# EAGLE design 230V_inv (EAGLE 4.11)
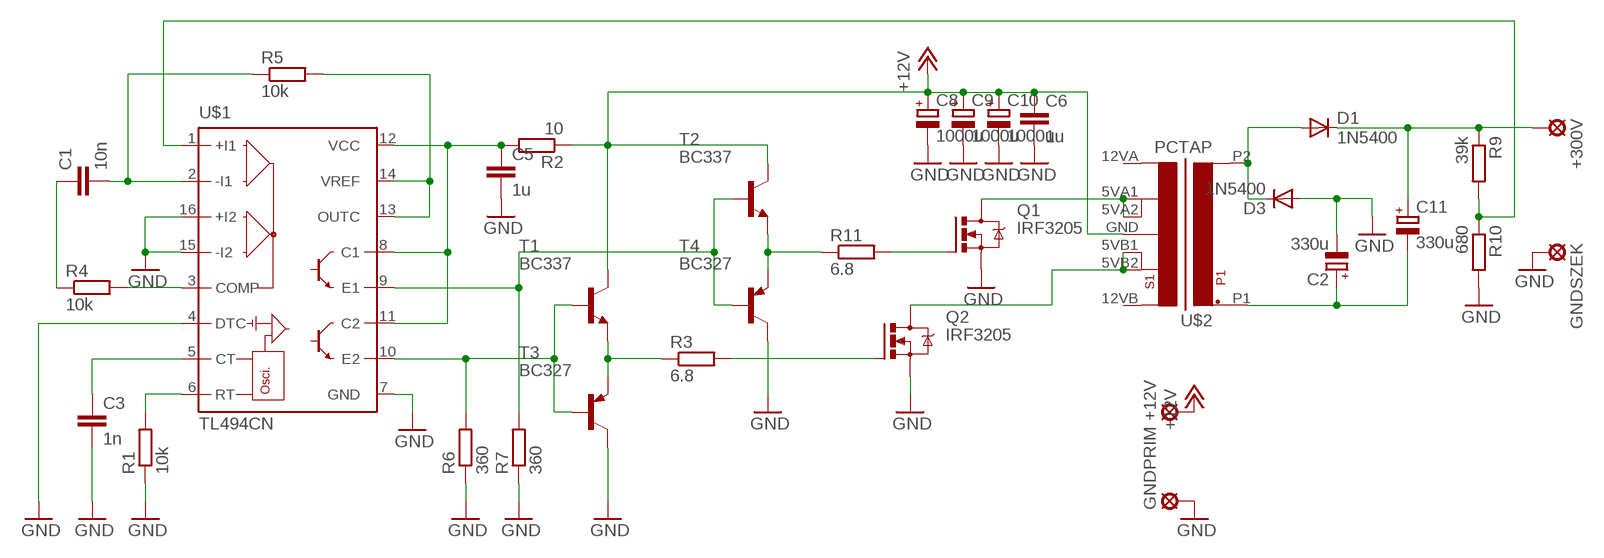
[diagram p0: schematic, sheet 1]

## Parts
+12V  SE14  [SE14]
+300V  SE14  [SE14]
C1  10n  C-EU025-025X050  [C025-025X050]
C2  330u  CPOL-EUE10-20  [EB20D]
C3  1n  C-EU025-025X050  [C025-025X050]
C5  1u  C-EU025-040X050  [C025-040X050]
C6  1u  C-EU025-040X050  [C025-040X050]
C8  1000u  CPOL-EUE5-10.5  [E5-10,5]
C9  1000u  CPOL-EUE5-10.5  [E5-10,5]
C10  1000u  CPOL-EUE5-10.5  [E5-10,5]
C11  330u  CPOL-EUE10-20  [EB20D]
D1  1N5400  [DO201-15]
D3  1N5400  [DO201-15]
GNDPRIM  SE14  [SE14]
GNDSZEK  SE14  [SE14]
Q1  IRF3205  IRF540  [TO220BV]
Q2  IRF3205  IRF540  [TO220BV]
R1  10k  R-EU_0204/5  [0204/5]
R2  10  R-EU_0204/5  [0204/5]
R3  6.8  R-EU_0204/5  [0204/5]
R4  10k  R-EU_0204/5  [0204/5]
R5  10k  R-EU_0204/5  [0204/5]
R6  360  R-EU_0204/5  [0204/5]
R7  360  R-EU_0204/5  [0204/5]
R9  39k  R-EU_0204/5  [0204/5]
R10  680  R-EU_0204/5  [0204/5]
R11  6.8  R-EU_0207/10  [0207/10]
T1  BC337  BC337-16-NPN-TO92-EBC  [TO92-EBC]
T2  BC337  BC337-16-NPN-TO92-EBC  [TO92-EBC]
T3  BC327  BC327-16-PNP-TO92-EBC  [TO92-EBC]
T4  BC327  BC327-16-PNP-TO92-EBC  [TO92-EBC]
U$1  TL494CN  [DIL16]
U$2  PCTAP  [PCTAP]

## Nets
+12V: +12V.MP C6.1 C8.+ C9.+ C10.+ R2.1 T1.C T2.C U$2.GND
GND: C2.- C3.2 C5.2 C6.2 C8.- C9.- C10.- D3.A GNDPRIM.MP GNDSZEK.MP Q1.S Q2.S R1.1 R6.1 R7.1 R10.2 T3.C T4.C U$1.4(DTC) U$1.7(GND) U$1.15(-I2) U$1.16(+I2)
N$1: R1.2 U$1.6(RT)
N$2: C3.1 U$1.5(CT)
N$3: R4.2 U$1.3(COMP)
N$4: C1.1 R4.1
N$5: C1.2 R5.1 U$1.2(-I1)
N$6: Q2.G R3.2
N$7: R5.2 U$1.13(OUTC) U$1.14(VREF)
N$8: C5.1 R2.2 U$1.8(C1) U$1.11(C2) U$1.12(VCC)
N$9: R6.2 T1.B T3.B U$1.10(E2)
N$10: Q1.G R11.2
N$11: D1.A D3.C U$2.P2
N$12: R3.1 T1.E T3.E
N$13: R7.2 T2.B T4.B U$1.9(E1)
N$14: R11.1 T2.E T4.E
N$15: C2.+ C11.- U$2.P1
N$16: +300V.MP C11.+ D1.C R9.1
N$18: Q2.D U$2.5VB1 U$2.5VB2
N$20: R9.2 R10.1 U$1.1(+I1)
N$22: Q1.D U$2.5VA1 U$2.5VA2
Unconnected: U$2.12VA U$2.12VB

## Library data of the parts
+12V +300V GNDPRIM GNDSZEK = solpad:SE14: SOLDER PAD
C1 C3 C5 C6 = rcl:C-EU: CAPACITOR, European symbol
C2 C8-C11 = rcl:CPOL-EU: POLARIZED CAPACITOR, European symbol
D1 D3 = diode:1N5400: DIODE
Q1 Q2 = transistor-power:IRF540: HEXFET Power MOSFET
R1-R7 R9-R11 = rcl:R-EU_: RESISTOR, European symbol
T1 T2 = transistor:*-NPN-: NPN Transistror
T3 T4 = transistor:*-PNP-: PNP Transistror
U$1 = linear:TL494*: SWITCHMODE Pulse Width Modulation Control Circuit NCV494B http://onsemi.com tl494-d.pdf
U$2 = trafo:PCTAP

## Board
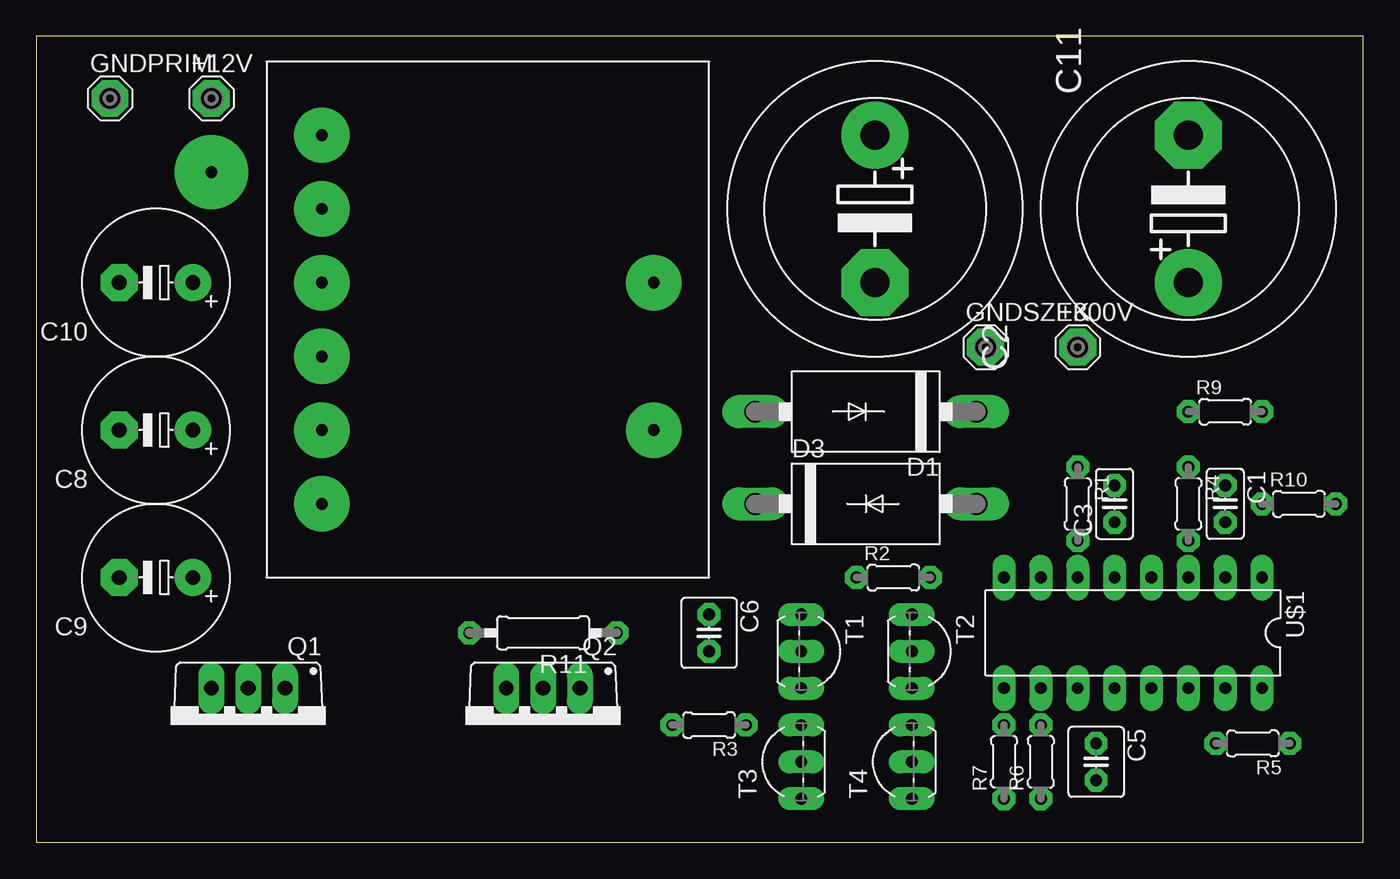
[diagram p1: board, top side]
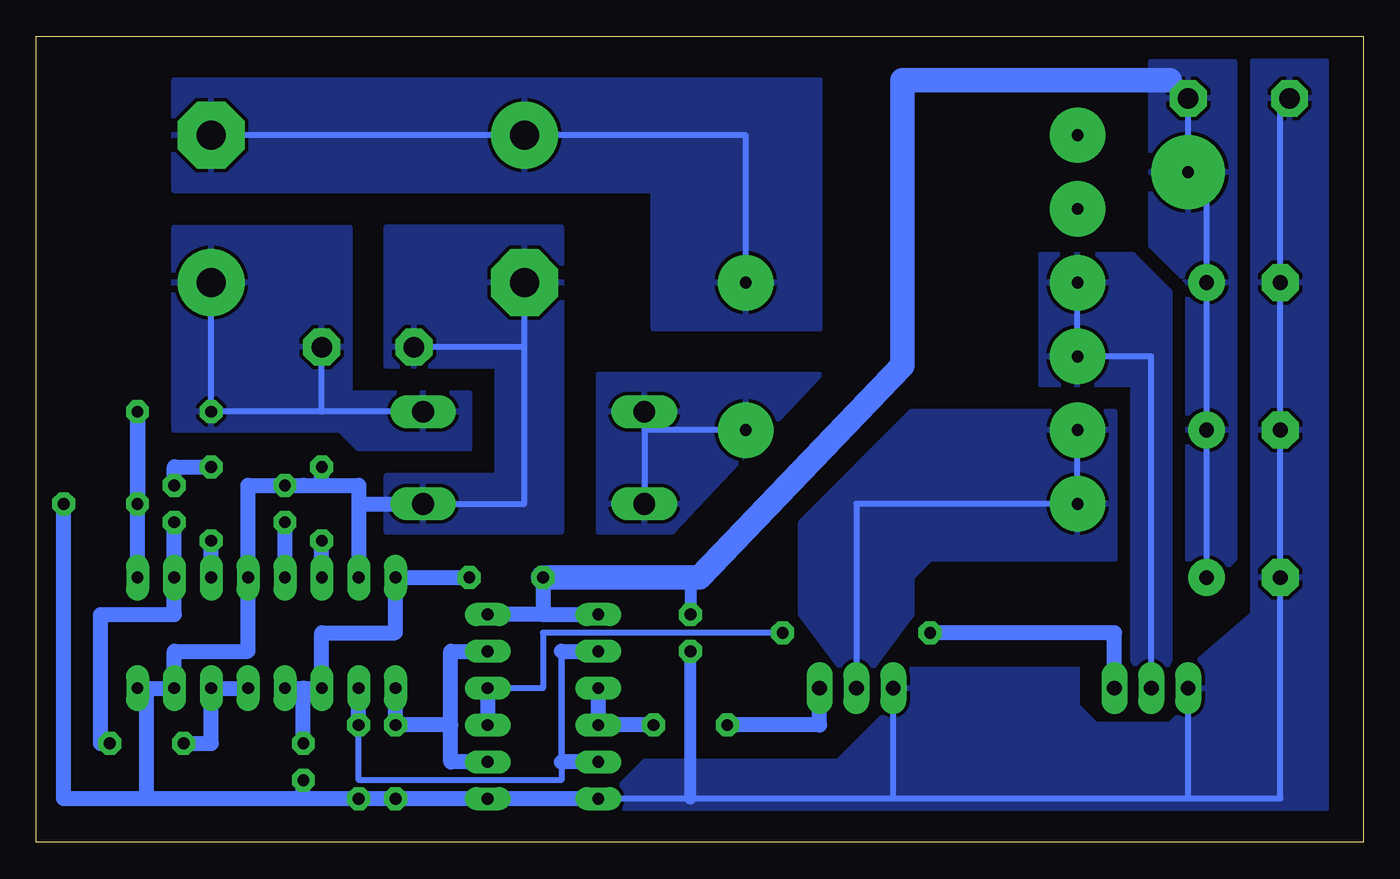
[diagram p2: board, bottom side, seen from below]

Size 91.42 x 55.55 mm. Coordinates in mm from the lower left corner, seen from the top.
Outline: 0,0 91.42,0 91.42,55.55 0,55.55 0,0
Copper layers (1*16): Top 0.035mm / dielectric 1.5mm / Bottom 0.035mm
Design rules "default": minimum track width 10mil, minimum drill 24mil, track to track 8mil, track to pad 8mil, pad to pad 8mil, via to via 8mil, smd to smd 8mil, copper to edge 40mil, drill to drill 8mil, minimum pad ring 15mil, minimum via ring 15mil, stop-mask expansion 4mil, vias tented up to drill 0mil, thermal gap 10mil

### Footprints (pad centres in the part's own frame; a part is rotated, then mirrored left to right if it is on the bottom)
SE14 = drill 1.397 pad 2.54 octagon: MP 0,0
C025-025X050 = drill 0.813 octagon: 1 -1.27,0; 2 1.27,0
EB20D = drill 2.007 pad 4.597 round: + -5.08,0 | drill 2.007 pad 4.597 octagon: - 5.08,0
C025-040X050 = drill 0.813 octagon: 1 -1.27,0; 2 1.27,0
E5-10,5 = drill 1.016 pad 2.54 round: + -2.54,0 | drill 1.016 pad 2.54 octagon: - 2.54,0
DO201-15 = drill 1.499 long: A 7.62,0; C -7.62,0
TO220BV = drill 1.016 long: D 0,-2.54; G -2.54,-2.54; S 2.54,-2.54
0204/5 = drill 0.813 octagon: 1 -2.54,0; 2 2.54,0
0207/10 = drill 0.813 octagon: 1 -5.08,0; 2 5.08,0
TO92-EBC = drill 0.813 long: B 0,-1.27; C -2.54,-1.27; E 2.54,-1.27
DIL16 = drill 0.813 long: 1 -8.89,-3.81; 2 -6.35,-3.81; 3 -3.81,-3.81; 4 -1.27,-3.81; 5 1.27,-3.81; 6 3.81,-3.81; 7 6.35,-3.81; 8 8.89,-3.81; 9 8.89,3.81; 10 6.35,3.81; 11 3.81,3.81; 12 1.27,3.81; 13 -1.27,3.81; 14 -3.81,3.81; 15 -6.35,3.81; 16 -8.89,3.81
PCTAP = drill 0.813 pad 3.81 round: 5VA1 10.16,0; 5VA2 15.24,0; 5VB1 20.32,0; 5VB2 25.4,0; 12VA 0,0; 12VB 5.08,0; P1 10.16,22.86; P2 20.32,22.86 | drill 0.813 pad 5.08 round: GND 2.54,-7.62

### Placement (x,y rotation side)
+12V  12.06,51.27 0 top
+300V  71.75,34.12 0 top
C1  81.91,23.33 270 top
C2  57.78,43.65 270 top
C3  74.29,23.33 90 top
C5  73.02,5.55 270 top
C6  46.35,14.44 270 top
C8  8.25,28.41 180 top
C9  8.25,18.25 180 top
C10  8.25,38.57 180 top
C11  79.37,43.65 90 top
D1  57.15,29.68 180 top
D3  57.15,23.33 0 top
GNDPRIM  5.08,51.27 0 top
GNDSZEK  65.4,34.12 0 top
Q1  14.6,8.09 180 top
Q2  34.92,8.09 180 top
R1  71.75,23.33 270 top
R2  59.05,18.25 0 top
R3  46.35,8.09 180 top
R4  79.37,23.33 270 top
R5  83.81,6.82 180 top
R6  69.21,5.55 90 top
R7  66.67,5.55 90 top
R9  81.91,29.68 0 top
R10  86.99,23.33 0 top
R11  34.92,14.44 180 top
T1  53.97,13.17 270 top
T2  61.59,13.17 270 top
T3  51.43,5.55 90 top
T4  59.05,5.55 90 top
U$1  75.56,14.44 180 top
U$2  19.68,48.73 270 top

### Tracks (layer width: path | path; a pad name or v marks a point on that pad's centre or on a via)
+12V
  Bottom 0.406: 56.51,15.71 53.97,15.71 | C9.+ C8.+ C10.+ 10.79,46.19 U$2.GND | U$2.GND +12V.MP | U$2.GND +12V.MP | +12V.MP 13.33,52.54
  Bottom 0.813: 46.35,18.25 C6.1
  Bottom 1.016: 56.51,15.71 T2.C | R2.1 56.51,15.71 | 56.51,15.71 T1.C
  Bottom 1.676: R2.1 46.35,18.25 45.72,18.25 31.74,32.85 31.74,52.54 13.33,52.54
  pour Bottom: 8.89,53.81 8.89,19.52 10.79,17.61 12.06,19.52 12.06,38.57 14.6,41.11 14.6,53.81
GND
  Bottom 0.406: D3.A 57.78,23.33 57.78,34.12 | 57.78,34.12 C2.- | 76.83,24.6 C3.2 73.02,24.6 | 12.06,3.01 Q1.S | 12.06,3.01 32.38,3.01 | 32.38,3.01 Q2.S | 32.38,3.01 46.35,3.01 T3.C | GNDPRIM.MP 5.71,51.27 C10.- C8.- C9.- 5.71,3.01 12.06,3.01 | 57.78,34.12 GNDSZEK.MP
  Bottom 0.813: 46.35,3.01 C6.2
  Bottom 1.016: T3.C T4.C R7.1 R6.1 73.02,3.01 | 71.75,24.6 R1.1 | 71.75,24.6 73.02,24.6 76.83,24.6 U$1.4 76.83,13.17 81.91,13.17 U$1.15 83.81,10.63 | 69.21,23.33 69.21,24.6 71.75,24.6 | 69.21,23.33 U$1.7 | 73.02,3.01 C5.2 | 83.81,10.63 U$1.16 | 73.02,3.01 83.81,3.01 | 83.81,3.01 83.81,10.63 | 69.21,23.33 D3.A | R10.2 89.53,3.01 83.81,3.01
  pour Bottom: 7.62,53.81 7.62,15.71 12.06,11.9 12.06,9.36 13.33,8.09 18.41,8.09 19.68,9.36 19.68,11.9 32.38,11.9 32.38,9.36 36.19,5.55 49.53,5.55 52.7,2.38 2.54,2.38 2.54,53.81
  pour Bottom: 67.3,25.23 67.3,21.42 55.24,21.42 55.24,42.38 67.3,42.38 67.3,32.85 59.69,32.85 59.69,25.23
N$1
  Bottom 1.016: U$1.6 R1.2
N$2
  Bottom 1.016: U$1.5 C3.1
N$3
  Bottom 1.016: U$1.3 R4.2
N$4
  Bottom 1.016: R4.1 81.91,25.87 C1.1
N$5
  Bottom 1.016: C1.2 U$1.2 81.91,15.71 86.99,15.71 86.99,6.82 R5.1
N$6
  Bottom 1.016: R3.2 37.46,8.09 Q2.G
N$7
  Bottom 1.016: U$1.13 U$1.14 79.37,6.82 R5.2
N$8
  Bottom 0.406: 73.02,10.63 U$1.12
  Bottom 1.016: U$1.12 U$1.11 71.75,14.44 66.67,14.44 U$1.8 R2.2 | C5.1 73.02,10.63
N$9
  Bottom 0.406: 55.24,5.55 55.24,13.17 55.24,4.28 69.21,4.28 R6.2
  Bottom 1.016: T3.B 55.24,5.55 | 55.24,13.17 T1.B | R6.2 U$1.10
N$10
  Bottom 1.016: R11.2 17.14,14.44 Q1.G
N$11
  Bottom 0.406: 49.53,28.41 D3.C | 49.53,28.41 D1.A | U$2.P2 49.53,28.41
  pour Bottom: 52.7,32.22 52.7,21.42 47.62,21.42 37.46,32.22
N$12
  Bottom 1.016: T1.E T3.E R3.1
N$13
  Bottom 0.406: R7.2 U$1.9
  Bottom 1.016: T2.B 62.86,13.17 62.86,8.09 | 62.86,8.09 62.86,5.55 T4.B | U$1.9 R7.2 62.86,8.09
N$14
  Bottom 0.406: T2.E 56.51,10.63 56.51,14.44 R11.1
  Bottom 1.016: T2.E T4.E
N$15
  Bottom 0.406: U$2.P1 42.54,48.73 C2.+ C11.-
  pour Bottom: 37.46,35.39 48.89,35.39 48.89,44.92 81.91,44.92 81.91,52.54 37.46,52.54
N$16
  Bottom 0.406: D1.C 71.75,29.68 | 71.75,29.68 R9.1 C11.+ | 71.75,29.68 +300V.MP
  pour Bottom: 64.13,30.95 61.59,30.95 61.59,27.14 69.21,27.14 70.48,28.41 81.91,28.41 81.91,42.38 69.84,42.38 69.84,30.95
N$18
  Bottom 0.406: U$2.5VB1 U$2.5VB2 34.92,23.33 Q2.D
  pour Bottom: 17.14,29.68 17.14,19.52 29.84,19.52 31.11,18.25 31.11,15.71 34.92,10.63 38.73,15.71 38.73,22.06 31.11,29.68
N$20
  Bottom 0.406: R9.2 R10.1
  Bottom 1.016: R9.2 R10.1 R9.2 | U$1.1 R9.2
N$22
  Bottom 0.406: U$2.5VA1 U$2.5VA2 14.6,33.49 Q1.D
  pour Bottom: 14.6,10 13.33,12.54 13.33,37.94 15.87,40.48 22.22,40.48 22.22,31.58 15.87,31.58 15.87,12.54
